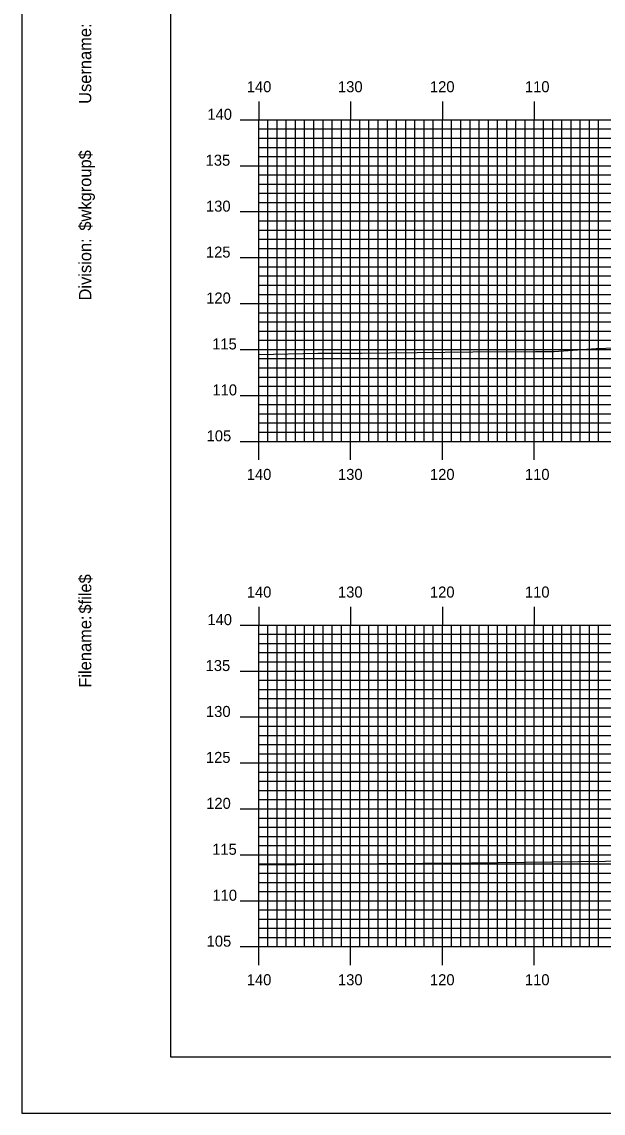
# Model space of a CAD drawing. Extents: x 1788943 to 1789287, y 442591 to 442811.
# Drawn here: x 1788943.4 to 1789006.7, y 442590.5 to 442709.3 of the extents above; entities that cross this region are included whole.
import ezdxf

# ---------------------------------------------------------------- set-up
doc = ezdxf.new("R2010")
doc.units = 0
for name, color, linetype in [('BORDER', 7, 'Continuous'), ('H_V ANNOTATION', 7, 'Continuous'), ('MAJOR', 7, 'Continuous'), ('MINOR', 7, 'Continuous'), ('PLOT BOUNDARY', 7, 'Continuous'), ('S_Roadway_Centerline', 7, 'Continuous')]:
    doc.layers.add(name, color=color, linetype=linetype)

msp = doc.modelspace()

# ---------------------------------------------------------------- linework, layer by layer
at = {"layer": 'BORDER'}
msp.add_lwpolyline([(1788959.56, 442596.67), (1789279.56, 442596.67), (1789279.56, 442806.67), (1788959.56, 442806.67)], close=True, dxfattribs=at)
at = {"layer": 'MAJOR'}
for p, q in [((1788969.16, 442700.67), (1788969.16, 442698.67)), ((1788979.16, 442700.67), (1788979.16, 442698.67)), ((1788989.16, 442700.67), (1788989.16, 442698.67)), ((1788999.16, 442700.67), (1788999.16, 442698.67)), ((1788967.15, 442698.67), (1788969.16, 442698.67)), ((1788969.16, 442698.67), (1789249.16, 442698.67)), ((1788969.16, 442663.67), (1788969.16, 442698.67)), ((1788969.16, 442663.67), (1788969.16, 442698.67)), ((1788969.16, 442698.67), (1789249.16, 442698.67)), ((1788979.16, 442663.67), (1788979.16, 442698.67)), ((1788989.16, 442663.67), (1788989.16, 442698.67)), ((1788999.16, 442663.67), (1788999.16, 442698.67)), ((1788967.15, 442693.67), (1788969.16, 442693.67)), ((1788969.16, 442693.67), (1789249.16, 442693.67)), ((1788967.15, 442688.67), (1788969.16, 442688.67)), ((1788969.16, 442688.67), (1789249.16, 442688.67)), ((1788967.15, 442683.67), (1788969.16, 442683.67)), ((1788969.16, 442683.67), (1789249.16, 442683.67)), ((1788967.15, 442678.67), (1788969.16, 442678.67)), ((1788969.16, 442678.67), (1789249.16, 442678.67)), ((1788967.15, 442673.67), (1788969.16, 442673.67)), ((1788969.16, 442673.67), (1789249.16, 442673.67)), ((1788967.15, 442668.67), (1788969.16, 442668.67)), ((1788969.16, 442668.67), (1789249.16, 442668.67)), ((1788967.15, 442663.67), (1788969.16, 442663.67)), ((1788969.16, 442663.67), (1789249.16, 442663.67)), ((1788969.16, 442663.67), (1789249.16, 442663.67)), ((1788969.16, 442661.66), (1788969.16, 442663.67)), ((1788979.16, 442661.66), (1788979.16, 442663.67)), ((1788989.16, 442661.66), (1788989.16, 442663.67)), ((1788999.16, 442661.66), (1788999.16, 442663.67)), ((1788969.16, 442645.67), (1788969.16, 442643.67)), ((1788979.16, 442645.67), (1788979.16, 442643.67)), ((1788989.16, 442645.67), (1788989.16, 442643.67)), ((1788999.16, 442645.67), (1788999.16, 442643.67)), ((1788967.15, 442643.67), (1788969.16, 442643.67)), ((1788969.16, 442643.67), (1789249.16, 442643.67)), ((1788969.16, 442608.67), (1788969.16, 442643.67)), ((1788969.16, 442608.67), (1788969.16, 442643.67)), ((1788969.16, 442643.67), (1789249.16, 442643.67)), ((1788979.16, 442608.67), (1788979.16, 442643.67)), ((1788989.16, 442608.67), (1788989.16, 442643.67)), ((1788999.16, 442608.67), (1788999.16, 442643.67)), ((1788967.15, 442638.67), (1788969.16, 442638.67)), ((1788969.16, 442638.67), (1789249.16, 442638.67)), ((1788967.15, 442633.67), (1788969.16, 442633.67)), ((1788969.16, 442633.67), (1789249.16, 442633.67)), ((1788967.15, 442628.67), (1788969.16, 442628.67)), ((1788969.16, 442628.67), (1789249.16, 442628.67)), ((1788967.15, 442623.67), (1788969.16, 442623.67)), ((1788969.16, 442623.67), (1789249.16, 442623.67)), ((1788967.15, 442618.67), (1788969.16, 442618.67)), ((1788969.16, 442618.67), (1789249.16, 442618.67)), ((1788967.15, 442613.67), (1788969.16, 442613.67)), ((1788969.16, 442613.67), (1789249.16, 442613.67)), ((1788967.15, 442608.67), (1788969.16, 442608.67)), ((1788969.16, 442608.67), (1789249.16, 442608.67)), ((1788969.16, 442608.67), (1789249.16, 442608.67)), ((1788969.16, 442606.66), (1788969.16, 442608.67)), ((1788979.16, 442606.66), (1788979.16, 442608.67)), ((1788989.16, 442606.66), (1788989.16, 442608.67)), ((1788999.16, 442606.66), (1788999.16, 442608.67))]:
    msp.add_line(p, q, dxfattribs=at)
at = {"layer": 'MINOR'}
for p, q in [((1788970.16, 442663.67), (1788970.16, 442698.67)), ((1788971.16, 442663.67), (1788971.16, 442698.67)), ((1788972.16, 442663.67), (1788972.16, 442698.67)), ((1788973.16, 442663.67), (1788973.16, 442698.67)), ((1788974.16, 442663.67), (1788974.16, 442698.67)), ((1788975.16, 442663.67), (1788975.16, 442698.67)), ((1788976.16, 442663.67), (1788976.16, 442698.67)), ((1788977.16, 442663.67), (1788977.16, 442698.67)), ((1788978.16, 442663.67), (1788978.16, 442698.67)), ((1788980.16, 442663.67), (1788980.16, 442698.67)), ((1788981.16, 442663.67), (1788981.16, 442698.67)), ((1788982.16, 442663.67), (1788982.16, 442698.67)), ((1788983.16, 442663.67), (1788983.16, 442698.67)), ((1788984.16, 442663.67), (1788984.16, 442698.67)), ((1788985.16, 442663.67), (1788985.16, 442698.67)), ((1788986.16, 442663.67), (1788986.16, 442698.67)), ((1788987.16, 442663.67), (1788987.16, 442698.67)), ((1788988.16, 442663.67), (1788988.16, 442698.67)), ((1788990.16, 442663.67), (1788990.16, 442698.67)), ((1788991.16, 442663.67), (1788991.16, 442698.67)), ((1788992.16, 442663.67), (1788992.16, 442698.67)), ((1788993.16, 442663.67), (1788993.16, 442698.67)), ((1788994.16, 442663.67), (1788994.16, 442698.67)), ((1788995.16, 442663.67), (1788995.16, 442698.67)), ((1788996.16, 442663.67), (1788996.16, 442698.67)), ((1788997.16, 442663.67), (1788997.16, 442698.67)), ((1788998.16, 442663.67), (1788998.16, 442698.67)), ((1789000.16, 442663.67), (1789000.16, 442698.67)), ((1789001.16, 442663.67), (1789001.16, 442698.67)), ((1789002.16, 442663.67), (1789002.16, 442698.67)), ((1789003.16, 442663.67), (1789003.16, 442698.67)), ((1789004.16, 442663.67), (1789004.16, 442698.67)), ((1789005.16, 442663.67), (1789005.16, 442698.67)), ((1789006.16, 442663.67), (1789006.16, 442698.67)), ((1788969.16, 442697.67), (1789249.16, 442697.67)), ((1788969.16, 442697.67), (1788971.16, 442697.67)), ((1788969.16, 442696.67), (1789249.16, 442696.67)), ((1788969.16, 442696.67), (1788971.16, 442696.67)), ((1788969.16, 442695.67), (1789249.16, 442695.67)), ((1788969.16, 442695.67), (1788971.16, 442695.67)), ((1788969.16, 442694.67), (1789249.16, 442694.67)), ((1788969.16, 442694.67), (1788971.16, 442694.67)), ((1788969.16, 442692.67), (1789249.16, 442692.67)), ((1788969.16, 442692.67), (1788971.16, 442692.67)), ((1788969.16, 442691.67), (1789249.16, 442691.67)), ((1788969.16, 442691.67), (1788971.16, 442691.67)), ((1788969.16, 442690.67), (1789249.16, 442690.67)), ((1788969.16, 442690.67), (1788971.16, 442690.67)), ((1788969.16, 442689.67), (1789249.16, 442689.67)), ((1788969.16, 442689.67), (1788971.16, 442689.67)), ((1788969.16, 442687.67), (1789249.16, 442687.67)), ((1788969.16, 442687.67), (1788971.16, 442687.67)), ((1788969.16, 442686.67), (1789249.16, 442686.67)), ((1788969.16, 442686.67), (1788971.16, 442686.67)), ((1788969.16, 442685.67), (1789249.16, 442685.67)), ((1788969.16, 442685.67), (1788971.16, 442685.67)), ((1788969.16, 442684.67), (1789249.16, 442684.67)), ((1788969.16, 442684.67), (1788971.16, 442684.67)), ((1788969.16, 442682.67), (1789249.16, 442682.67)), ((1788969.16, 442682.67), (1788971.16, 442682.67)), ((1788969.16, 442681.67), (1789249.16, 442681.67)), ((1788969.16, 442681.67), (1788971.16, 442681.67)), ((1788969.16, 442680.67), (1789249.16, 442680.67)), ((1788969.16, 442680.67), (1788971.16, 442680.67)), ((1788969.16, 442679.67), (1789249.16, 442679.67)), ((1788969.16, 442679.67), (1788971.16, 442679.67)), ((1788969.16, 442677.67), (1789249.16, 442677.67)), ((1788969.16, 442677.67), (1788971.16, 442677.67)), ((1788969.16, 442676.67), (1789249.16, 442676.67)), ((1788969.16, 442676.67), (1788971.16, 442676.67)), ((1788969.16, 442675.67), (1789249.16, 442675.67)), ((1788969.16, 442675.67), (1788971.16, 442675.67)), ((1788969.16, 442674.67), (1789249.16, 442674.67)), ((1788969.16, 442674.67), (1788971.16, 442674.67)), ((1788969.16, 442672.67), (1789249.16, 442672.67)), ((1788969.16, 442672.67), (1788971.16, 442672.67)), ((1788969.16, 442671.67), (1789249.16, 442671.67)), ((1788969.16, 442671.67), (1788971.16, 442671.67)), ((1788969.16, 442670.67), (1789249.16, 442670.67)), ((1788969.16, 442670.67), (1788971.16, 442670.67)), ((1788969.16, 442669.67), (1789249.16, 442669.67)), ((1788969.16, 442669.67), (1788971.16, 442669.67)), ((1788969.16, 442667.67), (1789249.16, 442667.67)), ((1788969.16, 442667.67), (1788971.16, 442667.67)), ((1788969.16, 442666.67), (1789249.16, 442666.67)), ((1788969.16, 442666.67), (1788971.16, 442666.67)), ((1788969.16, 442665.67), (1789249.16, 442665.67)), ((1788969.16, 442665.67), (1788971.16, 442665.67)), ((1788969.16, 442664.67), (1789249.16, 442664.67)), ((1788969.16, 442664.67), (1788971.16, 442664.67)), ((1788970.16, 442608.67), (1788970.16, 442643.67)), ((1788971.16, 442608.67), (1788971.16, 442643.67)), ((1788972.16, 442608.67), (1788972.16, 442643.67)), ((1788973.16, 442608.67), (1788973.16, 442643.67)), ((1788974.16, 442608.67), (1788974.16, 442643.67)), ((1788975.16, 442608.67), (1788975.16, 442643.67)), ((1788976.16, 442608.67), (1788976.16, 442643.67)), ((1788977.16, 442608.67), (1788977.16, 442643.67)), ((1788978.16, 442608.67), (1788978.16, 442643.67)), ((1788980.16, 442608.67), (1788980.16, 442643.67)), ((1788981.16, 442608.67), (1788981.16, 442643.67)), ((1788982.16, 442608.67), (1788982.16, 442643.67)), ((1788983.16, 442608.67), (1788983.16, 442643.67)), ((1788984.16, 442608.67), (1788984.16, 442643.67)), ((1788985.16, 442608.67), (1788985.16, 442643.67)), ((1788986.16, 442608.67), (1788986.16, 442643.67)), ((1788987.16, 442608.67), (1788987.16, 442643.67)), ((1788988.16, 442608.67), (1788988.16, 442643.67)), ((1788990.16, 442608.67), (1788990.16, 442643.67)), ((1788991.16, 442608.67), (1788991.16, 442643.67)), ((1788992.16, 442608.67), (1788992.16, 442643.67)), ((1788993.16, 442608.67), (1788993.16, 442643.67)), ((1788994.16, 442608.67), (1788994.16, 442643.67)), ((1788995.16, 442608.67), (1788995.16, 442643.67)), ((1788996.16, 442608.67), (1788996.16, 442643.67)), ((1788997.16, 442608.67), (1788997.16, 442643.67)), ((1788998.16, 442608.67), (1788998.16, 442643.67)), ((1789000.16, 442608.67), (1789000.16, 442643.67)), ((1789001.16, 442608.67), (1789001.16, 442643.67)), ((1789002.16, 442608.67), (1789002.16, 442643.67)), ((1789003.16, 442608.67), (1789003.16, 442643.67)), ((1789004.16, 442608.67), (1789004.16, 442643.67)), ((1789005.16, 442608.67), (1789005.16, 442643.67)), ((1789006.16, 442608.67), (1789006.16, 442643.67)), ((1788969.16, 442642.67), (1789249.16, 442642.67)), ((1788969.16, 442642.67), (1788971.16, 442642.67)), ((1788969.16, 442641.67), (1789249.16, 442641.67)), ((1788969.16, 442641.67), (1788971.16, 442641.67)), ((1788969.16, 442640.67), (1789249.16, 442640.67)), ((1788969.16, 442640.67), (1788971.16, 442640.67)), ((1788969.16, 442639.67), (1789249.16, 442639.67)), ((1788969.16, 442639.67), (1788971.16, 442639.67)), ((1788969.16, 442637.67), (1789249.16, 442637.67)), ((1788969.16, 442637.67), (1788971.16, 442637.67)), ((1788969.16, 442636.67), (1789249.16, 442636.67)), ((1788969.16, 442636.67), (1788971.16, 442636.67)), ((1788969.16, 442635.67), (1789249.16, 442635.67)), ((1788969.16, 442635.67), (1788971.16, 442635.67)), ((1788969.16, 442634.67), (1789249.16, 442634.67)), ((1788969.16, 442634.67), (1788971.16, 442634.67)), ((1788969.16, 442632.67), (1789249.16, 442632.67)), ((1788969.16, 442632.67), (1788971.16, 442632.67)), ((1788969.16, 442631.67), (1789249.16, 442631.67)), ((1788969.16, 442631.67), (1788971.16, 442631.67)), ((1788969.16, 442630.67), (1789249.16, 442630.67)), ((1788969.16, 442630.67), (1788971.16, 442630.67)), ((1788969.16, 442629.67), (1789249.16, 442629.67)), ((1788969.16, 442629.67), (1788971.16, 442629.67)), ((1788969.16, 442627.67), (1789249.16, 442627.67)), ((1788969.16, 442627.67), (1788971.16, 442627.67)), ((1788969.16, 442626.67), (1789249.16, 442626.67)), ((1788969.16, 442626.67), (1788971.16, 442626.67)), ((1788969.16, 442625.67), (1789249.16, 442625.67)), ((1788969.16, 442625.67), (1788971.16, 442625.67)), ((1788969.16, 442624.67), (1789249.16, 442624.67)), ((1788969.16, 442624.67), (1788971.16, 442624.67)), ((1788969.16, 442622.67), (1789249.16, 442622.67)), ((1788969.16, 442622.67), (1788971.16, 442622.67)), ((1788969.16, 442621.67), (1789249.16, 442621.67)), ((1788969.16, 442621.67), (1788971.16, 442621.67)), ((1788969.16, 442620.67), (1789249.16, 442620.67)), ((1788969.16, 442620.67), (1788971.16, 442620.67)), ((1788969.16, 442619.67), (1789249.16, 442619.67)), ((1788969.16, 442619.67), (1788971.16, 442619.67)), ((1788969.16, 442617.67), (1789249.16, 442617.67)), ((1788969.16, 442617.67), (1788971.16, 442617.67)), ((1788969.16, 442616.67), (1789249.16, 442616.67)), ((1788969.16, 442616.67), (1788971.16, 442616.67)), ((1788969.16, 442615.67), (1789249.16, 442615.67)), ((1788969.16, 442615.67), (1788971.16, 442615.67)), ((1788969.16, 442614.67), (1789249.16, 442614.67)), ((1788969.16, 442614.67), (1788971.16, 442614.67)), ((1788969.16, 442612.67), (1789249.16, 442612.67)), ((1788969.16, 442612.67), (1788971.16, 442612.67)), ((1788969.16, 442611.67), (1789249.16, 442611.67)), ((1788969.16, 442611.67), (1788971.16, 442611.67)), ((1788969.16, 442610.67), (1789249.16, 442610.67)), ((1788969.16, 442610.67), (1788971.16, 442610.67)), ((1788969.16, 442609.67), (1789249.16, 442609.67)), ((1788969.16, 442609.67), (1788971.16, 442609.67))]:
    msp.add_line(p, q, dxfattribs=at)
at = {"layer": 'PLOT BOUNDARY'}
msp.add_lwpolyline([(1788943.37, 442590.55), (1789283.37, 442590.55), (1789283.37, 442810.55), (1788943.37, 442810.55)], close=True, dxfattribs=at)
at = {"layer": 'S_Roadway_Centerline'}
for points in [[(1788969.16, 442673.13), (1788975.59, 442673.27), (1788980.34, 442673.28), (1788992.47, 442673.4), (1788999.28, 442673.44), (1789001.31, 442673.46), (1789005.91, 442673.77), (1789017.39, 442674.19), (1789027.74, 442674.25), (1789035.35, 442674.1), (1789038.18, 442674.24), (1789044.32, 442674.31), (1789063.26, 442674.6), (1789072.58, 442674.53)], [(1788969.16, 442617.57), (1788973.29, 442617.63), (1788982.18, 442617.71), (1788987.04, 442617.77), (1788992.32, 442617.81), (1789009.83, 442618), (1789019.42, 442618.16), (1789022.18, 442618.24), (1789023.54, 442618.24), (1789027.03, 442618.25), (1789042.37, 442618.42), (1789055.18, 442618.67), (1789079.24, 442619.18)]]:
    msp.add_lwpolyline(points, dxfattribs=at)

# ---------------------------------------------------------------- texts
at = {"layer": 'BORDER'}
for s, p in [('Username:', (1788950.93, 442700.4)), ('$wkgroup$', (1788950.93, 442686.6)), ('Division:', (1788950.93, 442679)), ('$file$', (1788950.93, 442644.92)), ('Filename:', (1788950.93, 442636.86))]:
    msp.add_text(s, height=1.339, rotation=90, dxfattribs=at).set_placement(p)
at = {"layer": 'H_V ANNOTATION'}
for s, p in [('140', (1788967.86, 442701.67)), ('130', (1788977.79, 442701.67)), ('120', (1788987.8, 442701.67)), ('110', (1788998.14, 442701.67)), ('140', (1788963.57, 442698.67)), ('135', (1788963.38, 442693.67)), ('130', (1788963.42, 442688.67)), ('125', (1788963.41, 442683.67)), ('120', (1788963.44, 442678.67)), ('115', (1788964.09, 442673.67)), ('110', (1788964.12, 442668.67)), ('105', (1788963.49, 442663.67)), ('140', (1788967.86, 442659.47)), ('130', (1788977.79, 442659.47)), ('120', (1788987.8, 442659.47)), ('110', (1788998.14, 442659.47)), ('140', (1788967.86, 442646.67)), ('130', (1788977.79, 442646.67)), ('120', (1788987.8, 442646.67)), ('110', (1788998.14, 442646.67)), ('140', (1788963.57, 442643.67)), ('135', (1788963.38, 442638.67)), ('130', (1788963.42, 442633.67)), ('125', (1788963.41, 442628.67)), ('120', (1788963.44, 442623.67)), ('115', (1788964.09, 442618.67)), ('110', (1788964.12, 442613.67)), ('105', (1788963.49, 442608.67)), ('140', (1788967.86, 442604.47)), ('130', (1788977.79, 442604.47)), ('120', (1788987.8, 442604.47)), ('110', (1788998.14, 442604.47))]:
    msp.add_text(s, height=1.2, dxfattribs=at).set_placement(p)
at = {"layer": 'MAJOR'}
for p in [(1788969.15, 442663.67), (1788969.15, 442608.67)]:
    msp.add_text('-', height=0.012, dxfattribs=at).set_placement(p)

doc.saveas('drawing.dxf')
